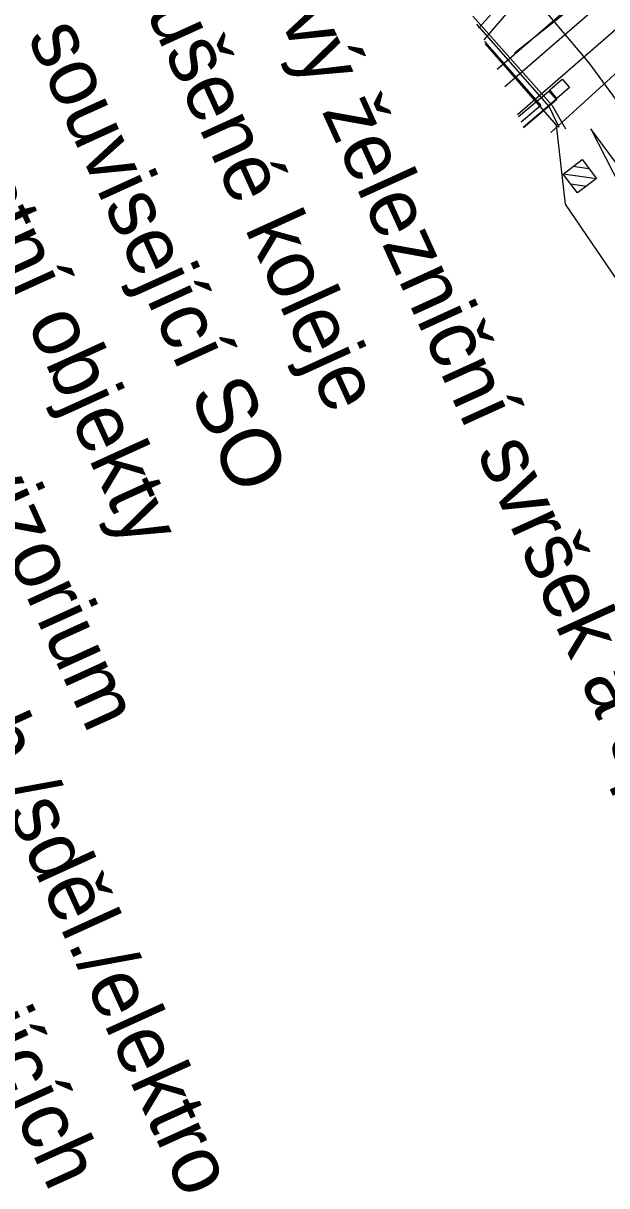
# Model space of a CAD drawing. Extents: x -735603 to -735159, y -1043062 to -1042557.
# Drawn here: x -735536.9 to -735512.3, y -1042742.34 to -1042693.35 of the extents above; entities that cross this region are included whole.
import ezdxf

# ---------------------------------------------------------------- set-up
doc = ezdxf.new("R2010")
doc.units = 0
for name, color, linetype in [('05_vnitřní kresba', 7, 'Continuous'), ('095_LEGENDA', 7, 'Continuous'), ('6-PRE_TR', 7, 'Continuous'), ('9-O2_metalicky_kabel_zamereny', 7, 'Continuous'), ('komunikace_chodníky', 7, 'Continuous'), ('mosty', 7, 'Continuous'), ('ochrany podzemní', 7, 'Continuous'), ('osa koleje a její popis', 7, 'Continuous'), ('ploty_zdi_zábradlí_svodidla_vchody', 7, 'Continuous'), ('přejezd_přechod', 7, 'Continuous'), ('stožáry  trakčního vedení', 7, 'Continuous'), ('vedení a zařízení neurčená', 7, 'Continuous'), ('Vrstva 26', 7, 'Continuous')]:
    doc.layers.add(name, color=color, linetype=linetype)

msp = doc.modelspace()

# ---------------------------------------------------------------- linework, layer by layer
at = {"layer": '05_vnitřní kresba'}
for p, q in [((-735516.182, -1042694.602), (-735512.38, -1042691.58)), ((-735514.66, -1042697.952), (-735509.86, -1042693.59))]:
    msp.add_line(p, q, dxfattribs=at)
at = {"layer": '6-PRE_TR'}
for points in [[(-735514.412, -1042697.65), (-735517.408, -1042694.227)], [(-735368.816, -1042801.11), (-735371.224, -1042799.657), (-735382.643, -1042790.598), (-735384.7, -1042787.091), (-735386.388, -1042783.374), (-735406.643, -1042767.795), (-735426.649, -1042751.367), (-735446.216, -1042735.189), (-735472.581, -1042714.884), (-735489.744, -1042702.609), (-735495.194, -1042702.694), (-735498.802, -1042700.681), (-735498.175, -1042704.367), (-735499.811, -1042707.737), (-735506.585, -1042711.901), (-735514.038, -1042700.981), (-735514.412, -1042697.65), (-735517.408, -1042694.227)]]:
    msp.add_lwpolyline(points, dxfattribs=at)
at = {"layer": '9-O2_metalicky_kabel_zamereny'}
for points in [[(-735380.17, -1042689.37), (-735422.06, -1042678.58), (-735461.68, -1042666.29), (-735463.87, -1042665.61), (-735477.24, -1042663.28), (-735481.97, -1042664.88), (-735495.24, -1042669.37), (-735498.84, -1042672.34), (-735517.487, -1042694.055)], [(-735495.24, -1042669.37), (-735498.84, -1042672.34), (-735517.487, -1042694.055)]]:
    msp.add_lwpolyline(points, dxfattribs=at)
at = {"layer": 'komunikace_chodníky'}
msp.add_lwpolyline([(-735517.709, -1042693.565), (-735508.579, -1042683.498), (-735498.648, -1042672.473), (-735494.29, -1042669.155), (-735481.15, -1042664.924), (-735466.575, -1042667.17), (-735452.243, -1042673.199), (-735450.421, -1042670.34)], dxfattribs=at)
at = {"layer": 'mosty'}
msp.add_line((-735515.816, -1042697.732), (-735514.405, -1042696.523), dxfattribs=at)
for points in [[(-735501.261, -1042677.584), (-735506.675, -1042684.551), (-735506.598, -1042684.632), (-735512.307, -1042691.313), (-735516.916, -1042695.31)], [(-735516.593, -1042696.023), (-735512.307, -1042692.295), (-735506.223, -1042685.496)], [(-735516.055, -1042697.207), (-735511.491, -1042693.237), (-735505.407, -1042686.438)], [(-735514.701, -1042696.161), (-735514.174, -1042695.718), (-735513.865, -1042696.062), (-735514.405, -1042696.523)], [(-735515.81, -1042697.746), (-735514.422, -1042696.571), (-735514.739, -1042696.229), (-735516.012, -1042697.302)], [(-735514.422, -1042696.571), (-735514.405, -1042696.523), (-735514.701, -1042696.161), (-735514.739, -1042696.229)]]:
    msp.add_lwpolyline(points, dxfattribs=at)
at = {"layer": 'ochrany podzemní'}
msp.add_lwpolyline([(-735517.943, -1042693.05), (-735514.597, -1042696.826), (-735514.035, -1042697.811)], dxfattribs=at)
at = {"layer": 'osa koleje a její popis'}
msp.add_lwpolyline([(-735464.308, -1042786.652), (-735472.802, -1042763.644), (-735480.68, -1042746.31), (-735490.611, -1042727.894), (-735501.392, -1042710.934), (-735513.035, -1042695.027), (-735521.726, -1042684.722)], dxfattribs=at)
at = {"layer": 'ploty_zdi_zábradlí_svodidla_vchody'}
msp.add_lwpolyline([(-735517.456, -1042694.121), (-735515.078, -1042696.824), (-735515.911, -1042697.523)], dxfattribs=at)
at = {"layer": 'přejezd_přechod'}
msp.add_lwpolyline([(-735465.73, -1042787.687), (-735474.297, -1042764.943), (-735482.57, -1042747.028), (-735492.141, -1042728.856), (-735502.618, -1042711.795), (-735512.97, -1042697.809), (-735510.798, -1042702.056), (-735503.26, -1042712.424), (-735492.562, -1042728.949), (-735483.023, -1042747.17), (-735475.133, -1042765.421), (-735466.205, -1042787.745)], dxfattribs=at)
at = {"layer": 'stožáry  trakčního vedení'}
for p, q in [((-735513.713, -1042699.384), (-735513.058, -1042699.473)), ((-735514.134, -1042699.706), (-735512.737, -1042699.894)), ((-735513.817, -1042700.127), (-735513.154, -1042700.216))]:
    msp.add_line(p, q, dxfattribs=at)
msp.add_lwpolyline([(-735513.342, -1042699.101), (-735512.735, -1042699.896), (-735513.53, -1042700.503), (-735514.137, -1042699.708)], close=True, dxfattribs=at)
msp.add_lwpolyline([(-735513.342, -1042699.101), (-735512.735, -1042699.896), (-735513.53, -1042700.503), (-735514.137, -1042699.708), (-735513.342, -1042699.101)], dxfattribs=at)
at = {"layer": 'vedení a zařízení neurčená'}
msp.add_lwpolyline([(-735517.787, -1042693.395), (-735514.72, -1042696.881), (-735514.323, -1042697.733)], dxfattribs=at)
at = {"layer": 'Vrstva 26'}
for points in [[(-735514.412, -1042697.65), (-735517.408, -1042694.227)], [(-735368.816, -1042801.11), (-735371.224, -1042799.657), (-735382.643, -1042790.598), (-735384.7, -1042787.091), (-735386.388, -1042783.374), (-735406.643, -1042767.795), (-735426.649, -1042751.367), (-735446.216, -1042735.189), (-735472.581, -1042714.884), (-735489.744, -1042702.609), (-735495.194, -1042702.694), (-735498.802, -1042700.681), (-735498.175, -1042704.367), (-735499.811, -1042707.737), (-735506.585, -1042711.901), (-735514.038, -1042700.981), (-735514.412, -1042697.65), (-735517.408, -1042694.227)]]:
    msp.add_lwpolyline(points, dxfattribs=at)

# ---------------------------------------------------------------- texts
at = {"layer": '095_LEGENDA'}
for s, p in [('nový železniční svršek a spodek', (-735527.638, -1042689.767)), ('rušené koleje', (-735532.191, -1042691.835)), ('související SO', (-735536.743, -1042693.903)), ('mostní objekty', (-735541.295, -1042695.971)), ('mostní provizorium', (-735545.806, -1042697.635)), ('kabelové trasy zab./sděl./elektro', (-735549.878, -1042699.485)), ('demolice v rámci souvisejících SO', (-735554.43, -1042701.553))]:
    msp.add_text(s, height=2.5, rotation=294.4315, dxfattribs=at).set_placement(p)

doc.saveas('drawing.dxf')
